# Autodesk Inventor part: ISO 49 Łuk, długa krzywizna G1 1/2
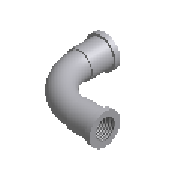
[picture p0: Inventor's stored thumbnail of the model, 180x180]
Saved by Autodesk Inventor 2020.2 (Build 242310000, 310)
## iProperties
Manager: www.cadconsulting.pl
Company: Fabian Stasiak CAD Consulting
Created: 2014-02
Part Number: ISO 49 Łuk, długa krzywizna G1 1/2
Material: Żelazo, ciągliwe
Description: Elementy z żeliwa ciągliwego - Łuki z długą krzywizną G1
Document SubType Name: Modeling
Standard: ISO 49
Designer: F.Stasiak
Standard Revision: Second edition 1994-12-15
Standards Organization: ISO
Language: pl-PL
Size Designation: 1/2
Categories: <MemberInstance><Categories><Category DisplayName="Rury cienko- i grubościenne" InternalName="4347fa0f-2144-441d-94cd-e3e15c92b736" Mnemonic="TUBEANDPIPE"><Cate
Density: 7.15 g/cm^3
Appearance: Częściowo polerowana
Catalog Web Link: www.expertbooks.pl
NAME: PIPING: ISO 49 Long Sweep Bend G1
DATA: <meta><inlinegroups number="0" deflen="0"></inlinegroups><connections number="2"></connections><angles><a>1.57079632679489</a></angles></meta>
IsCustomPart: 0
Author: F.Stasiak
Subject: Zbiór ćwiczeń. Autodesk Inventor 2020. Kurs Professional
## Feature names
1. Revolution1
2. Revolution2
3. Sweep1
## Parameters: a = 55 mm, MD = 18.631 mm, H = 28.21 mm, d0 = 18.631 mm, d1 = 28.21 mm, d2 = 4.34 mm, d3 = 19.5 mm, d4 = 0.3124 mm, d26 = 90 deg, d5 = 18.631 mm, d6 = 23.87 mm, d7 = 28.21 mm, d8 = 4.34 mm, d9 = 19.5 mm, d10 = 0.3124 mm, d37 = 90 deg, EE = 4.34 mm, D = 21.7 mm, z = 42 mm, d11 = 23.87 mm, d12 = 55 mm, d13 = 0, d83 = 25.4 mm, d84 = 0, d85 = 25.4 mm, d86 = 0, d14 = 55 mm, d15 = 13 mm, d16 = 13 mm, d17 = 21.7 mm, d91 = 0, Size_Designation = 5 mm
